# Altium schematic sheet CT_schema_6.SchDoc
size 578 x 363 mm
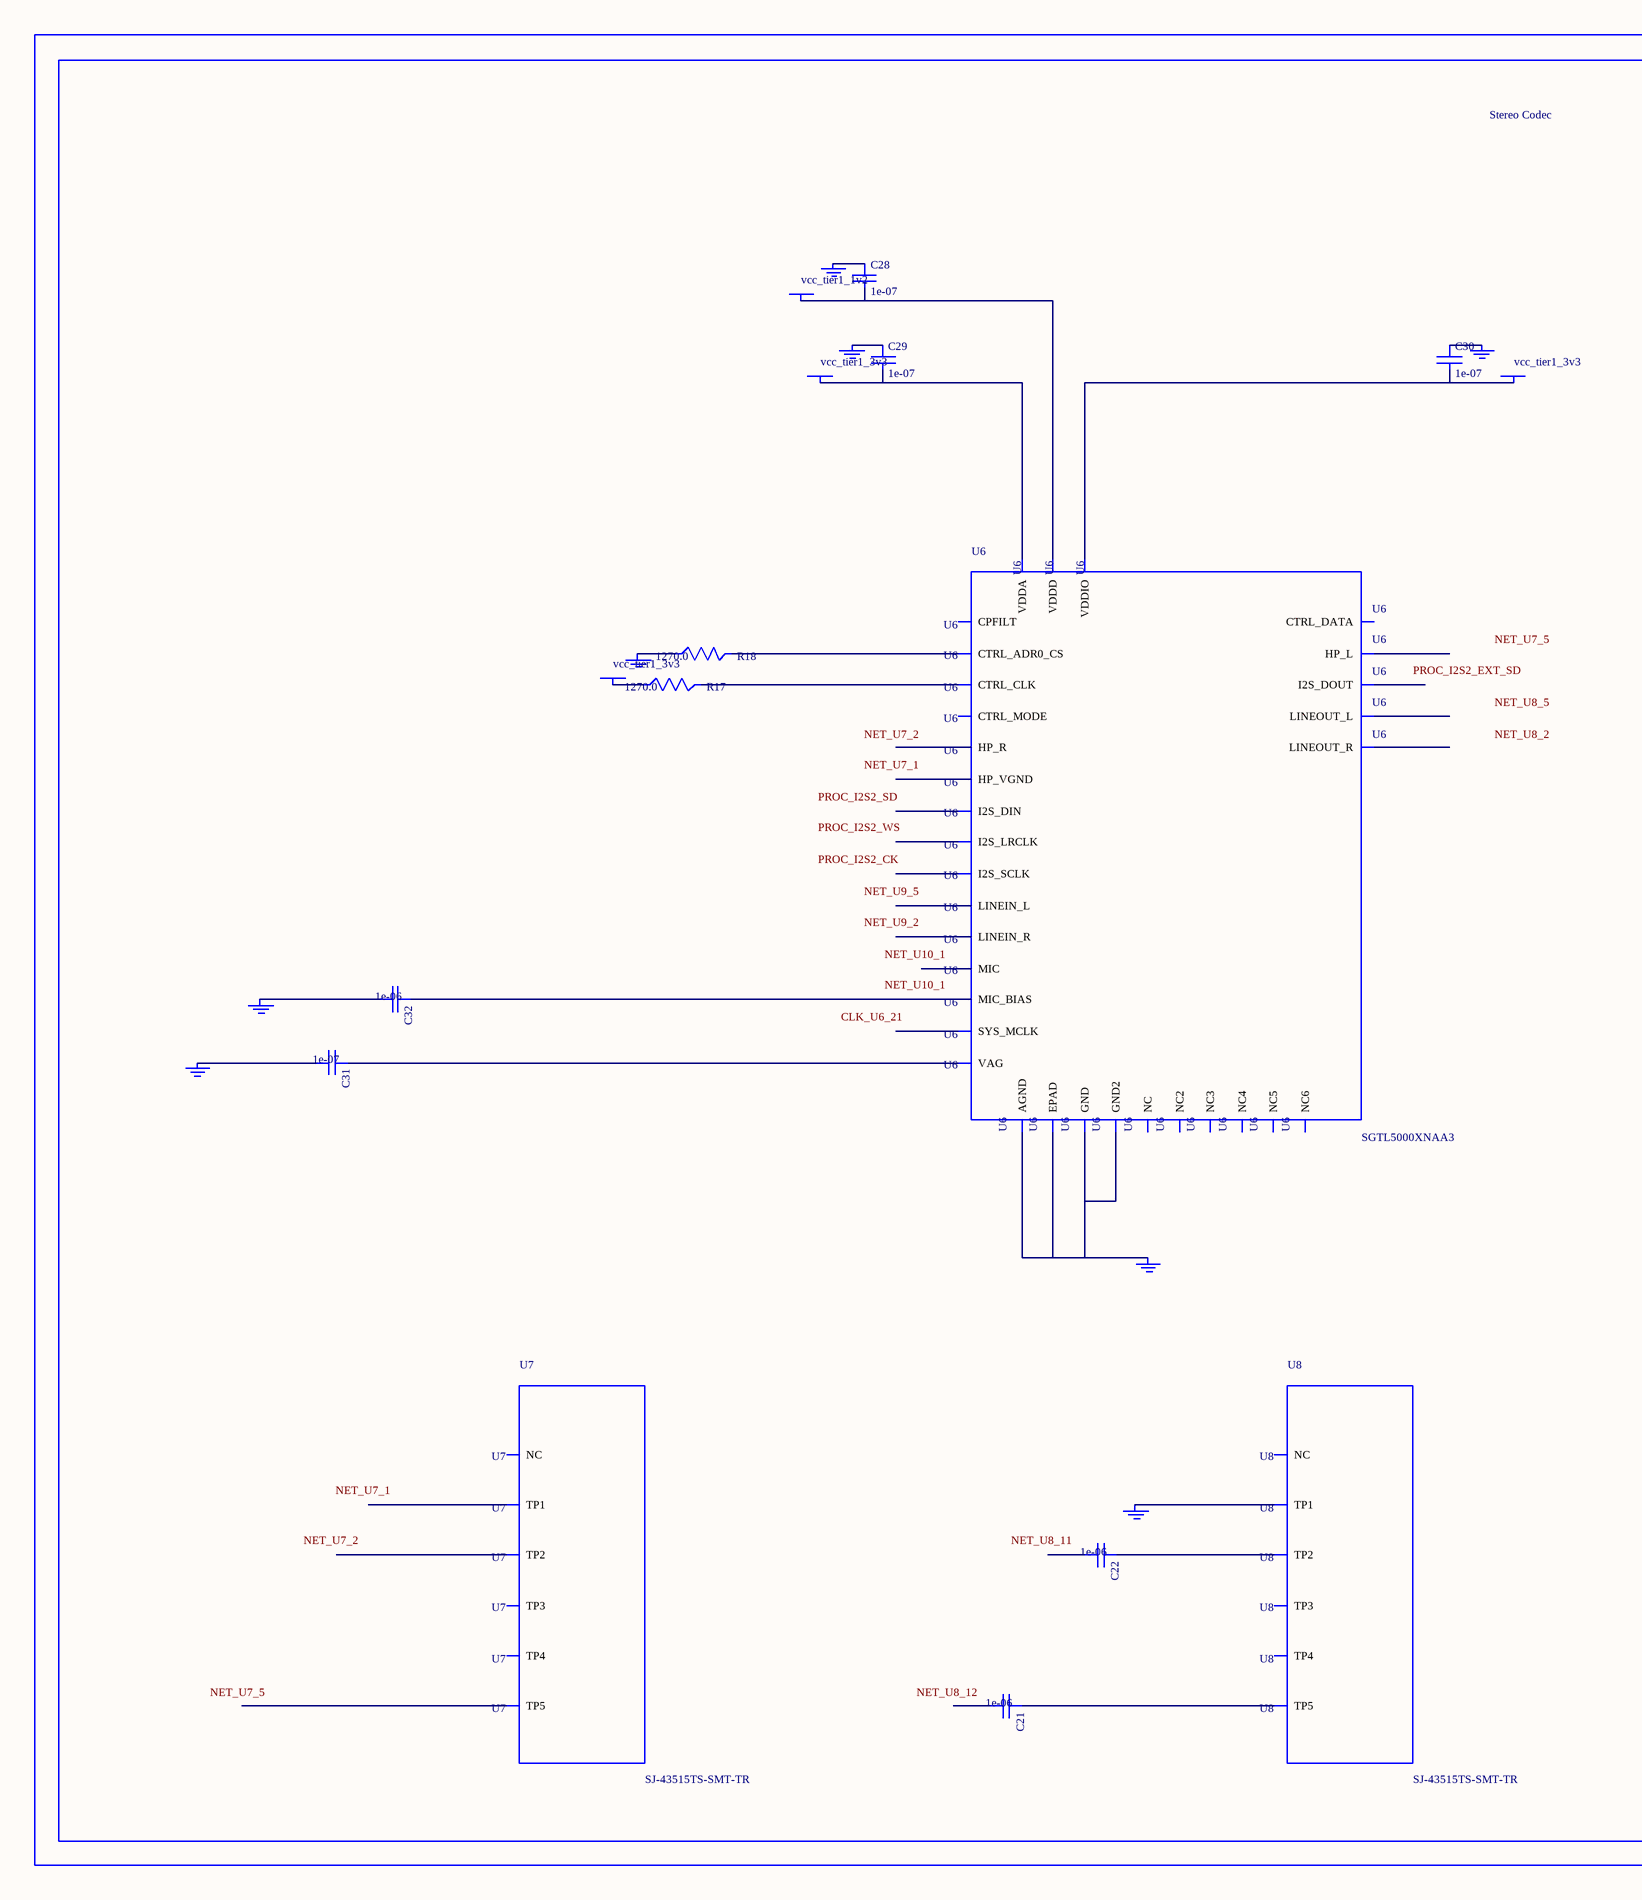
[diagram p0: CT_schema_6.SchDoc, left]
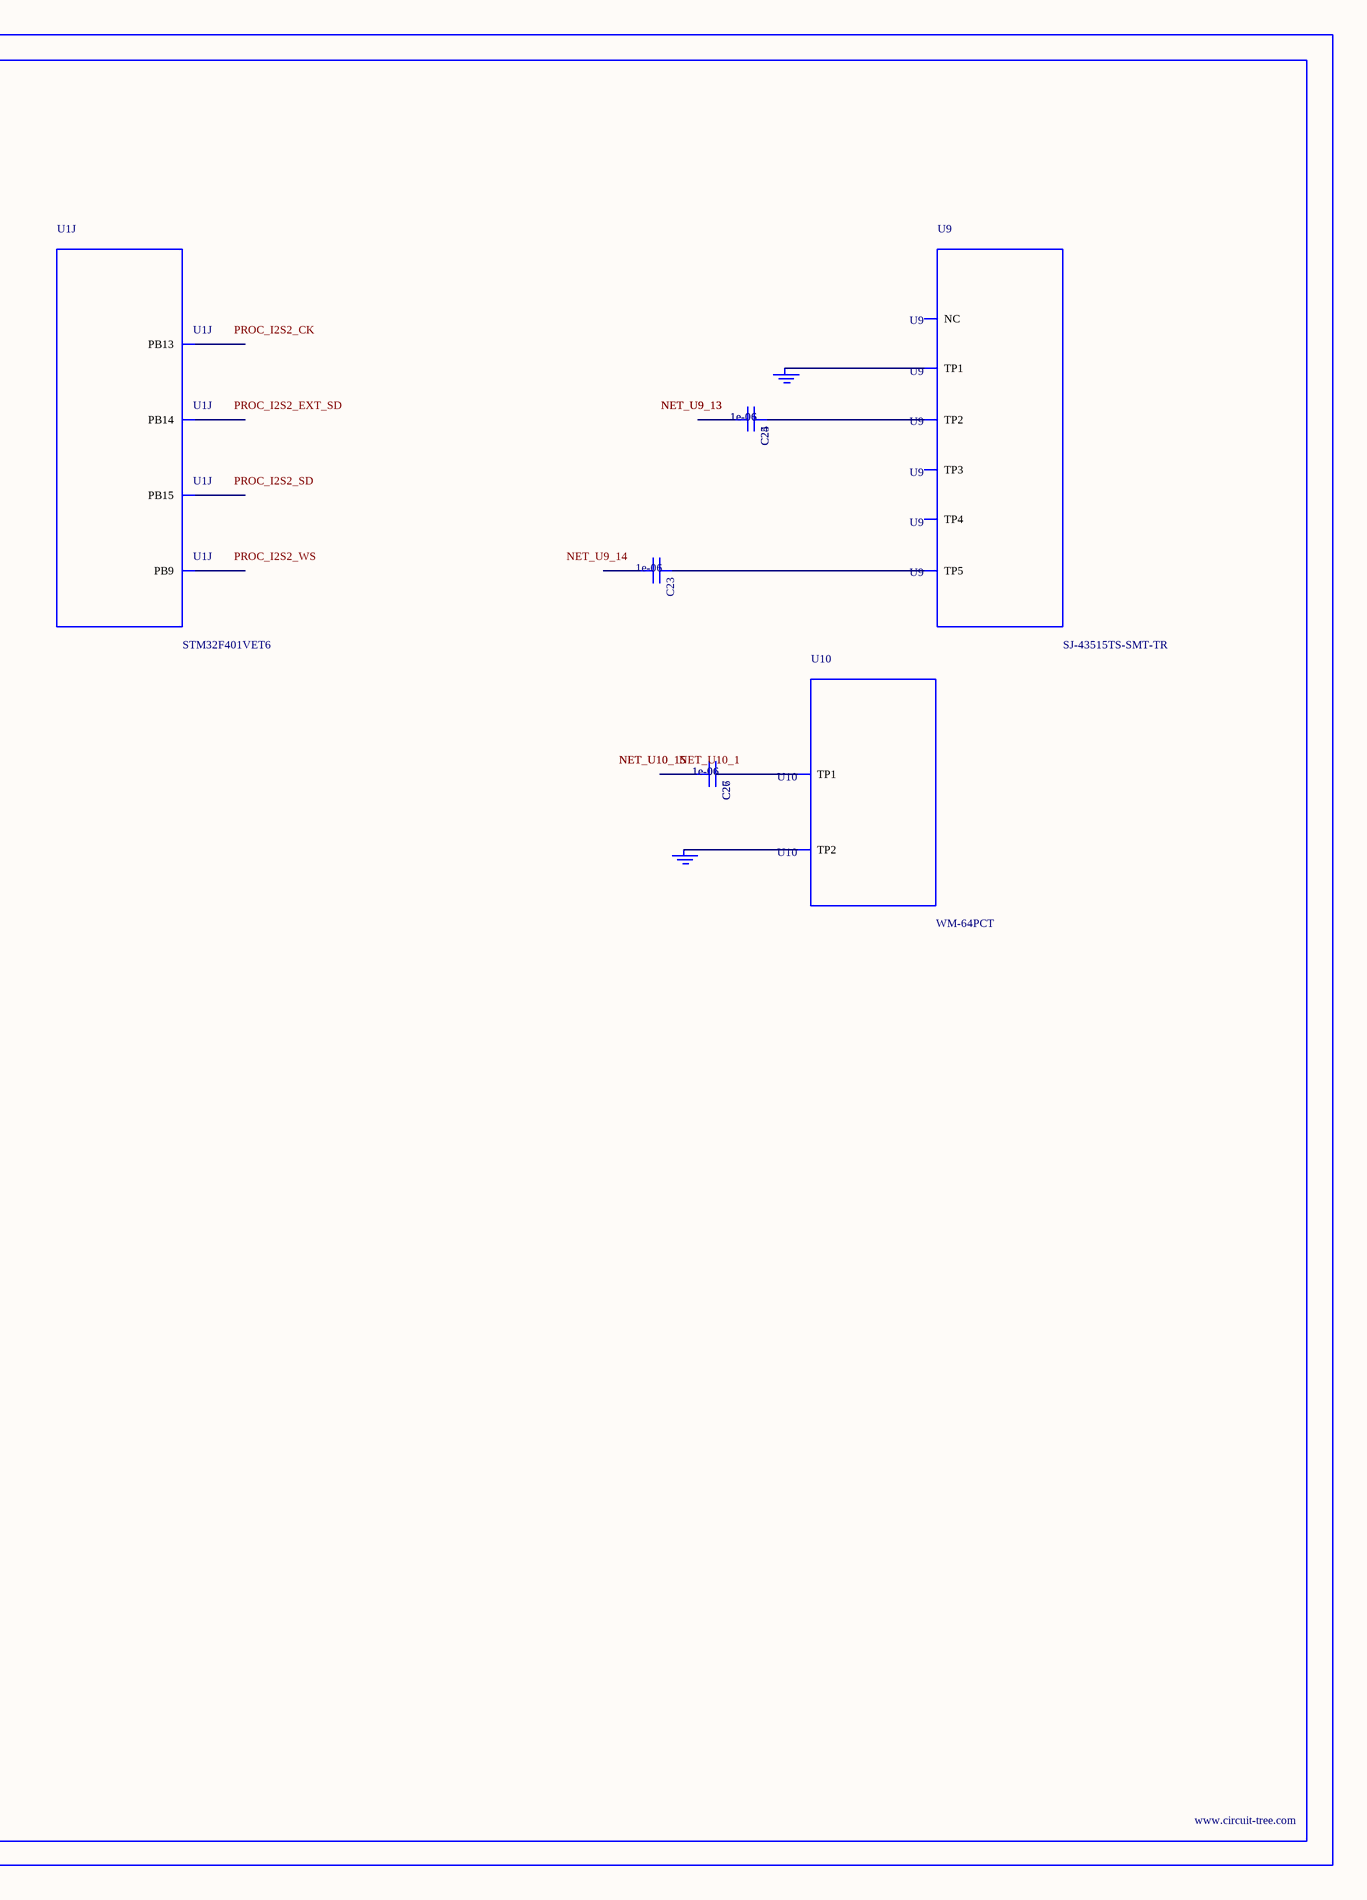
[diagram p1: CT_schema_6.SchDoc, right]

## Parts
BORDER5  (no value)
C21  1e-06  [C0603]
C22  1e-06  [C0603]
C23  1e-06  [C0603]
C24  1e-06  [C0603]
C25  1e-06  [C0603]
C26  1e-06  [C0603]
C27  1e-06  [C0603]
C28  1e-07  [C0402]
C29  1e-07  [C0402]
C30  1e-07  [C0402]
C31  1e-07  [C0402]
C32  1e-06  [C0603]
GND_INSTANCE_5_0  (no value)
GND_INSTANCE_5_1  (no value)
GND_INSTANCE_5_2  (no value)
GND_INSTANCE_5_3  (no value)
GND_INSTANCE_5_4  (no value)
GND_INSTANCE_5_5  (no value)
GND_INSTANCE_5_6  (no value)
GND_INSTANCE_5_7  (no value)
GND_INSTANCE_5_8  (no value)
GND_INSTANCE_5_9  (no value)
GND_INSTANCE_5_10  (no value)
POWER_INSTANCE_5_0  vcc_tier1_3v3
POWER_INSTANCE_5_1  vcc_tier1_3v3
POWER_INSTANCE_5_2  vcc_tier1_3v3
POWER_INSTANCE_5_3  vcc_tier1_1v2
R17  1270.0  [R0603]
R18  1270.0  [R0603]
U1  STM32F401VET6  [LQFP100]  (part J of 10)
U6  SGTL5000XNAA3  [QFN-32]
U7  SJ-43515TS-SMT-TR  [SJ-43515TS-SMT-TR]
U8  SJ-43515TS-SMT-TR  [SJ-43515TS-SMT-TR]
U9  SJ-43515TS-SMT-TR  [SJ-43515TS-SMT-TR]
U10  WM-64PCT  [WM-64PC]

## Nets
NetC21_1: C21.1 U8.5(TP5)
NetC22_1: C22.1 U8.2(TP2)
NetC23_1: C23.1 U9.5(TP5)
NetC24_1: C24.1 C25.1 U9.2(TP2)
NetC24_2: C24.2 C25.2
NetC26_1: C26.1 C27.1 U10.1(TP1)
NetC26_2: C26.2 C27.2
NetC28_1: C28.1 GND_INSTANCE_5_5.0(GND)
NetC28_2: C28.2 POWER_INSTANCE_5_3.0(PWR) U6.30(VDDD)
NetC29_1: C29.1 GND_INSTANCE_5_1.0(GND)
NetC29_2: C29.2 POWER_INSTANCE_5_0.0(PWR) U6.5(VDDA)
NetC30_1: C30.1 GND_INSTANCE_5_4.0(GND)
NetC30_2: C30.2 POWER_INSTANCE_5_1.0(PWR) U6.20(VDDIO)
NetC31_1: C31.1 U6.10(VAG)
NetC31_2: C31.2 GND_INSTANCE_5_2.0(GND)
NetC32_1: C32.1 U6.16(MIC_BIAS)
NetC32_2: C32.2 GND_INSTANCE_5_3.0(GND)
NetGND_INSTANCE_5_0_0: GND_INSTANCE_5_0.0(GND) U6.1(GND) U6.3(GND2) U6.7(AGND) U6.EXP(EPAD)
NetGND_INSTANCE_5_6_0: GND_INSTANCE_5_6.0(GND) R18.1
NetGND_INSTANCE_5_7_0: GND_INSTANCE_5_7.0(GND) U8.1(TP1)
NetGND_INSTANCE_5_8_0: GND_INSTANCE_5_8.0(GND) GND_INSTANCE_5_9.0(GND) U9.1(TP1)
NetGND_INSTANCE_5_10_0: GND_INSTANCE_5_10.0(GND) U10.2(TP2)
NetPOWER_INSTANCE_5_2_0: POWER_INSTANCE_5_2.0(PWR) R17.1
NetR17_2: R17.2 U6.29(CTRL_CLK)
NetR18_2: R18.2 U6.31(CTRL_ADR0_CS)

Not connected (* = marked no-connect by the designer): C21 2; C22 2; C23 2; U1 52(PB13) 53(PB14) 54(PB15) 96(PB9); U6 2(HP_R) 4(HP_VGND) 6(HP_L) 8(NC) 9(NC2) 11(LINEOUT_R) 12(LINEOUT_L) 13(LINEIN_R) 14(LINEIN_L) 15(MIC) 17(NC3) 18(CPFILT) 19(NC4) 21(SYS_MCLK) 22(NC5) 23(I2S_LRCLK) 24(I2S_SCLK) 25(I2S_DOUT) 26(I2S_DIN) 27(CTRL_DATA) 28(NC6) 32(CTRL_MODE); U7 1(TP1) 2(TP2) 3(TP3) 4(TP4) 5(TP5) 6(NC); U8 3(TP3) 4(TP4) 6(NC); U9 3(TP3) 4(TP4) 6(NC)

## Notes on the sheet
- Labels drawn without touching a wire or pin: CLK_U6_21, NET_U7_1, NET_U7_2, NET_U7_5, NET_U8_2, NET_U8_5, NET_U8_11, NET_U8_12, NET_U9_2, NET_U9_5, NET_U9_14, NET_U10_1, PROC_I2S2_CK, PROC_I2S2_EXT_SD, PROC_I2S2_SD, PROC_I2S2_WS

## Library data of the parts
BORDER5 = BORDER_PAGE5
C21-C27 C32 = C0603C105K3RACTU
C28-C31 = C0402C104K3RACTU
GND_INSTANCE_5_0-GND_INSTANCE_5_10 = GND
POWER_INSTANCE_5_0-POWER_INSTANCE_5_3 = PWR
R17 R18 = RC0603FR-071K27L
